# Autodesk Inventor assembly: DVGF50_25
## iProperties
Created: 2010-04
Part Number: DVGF50_25
Document SubType Name: Assembly
Designer: TB
Mass: 740.324 g
Surface Area: 1369.44 cm^2
Volume: 740.324 cm^3
Density: 1 g/cm^3
Description: KM DVGF 50/25 - 100 mm
Slaglengde: 100.000 mm
Author: TB
